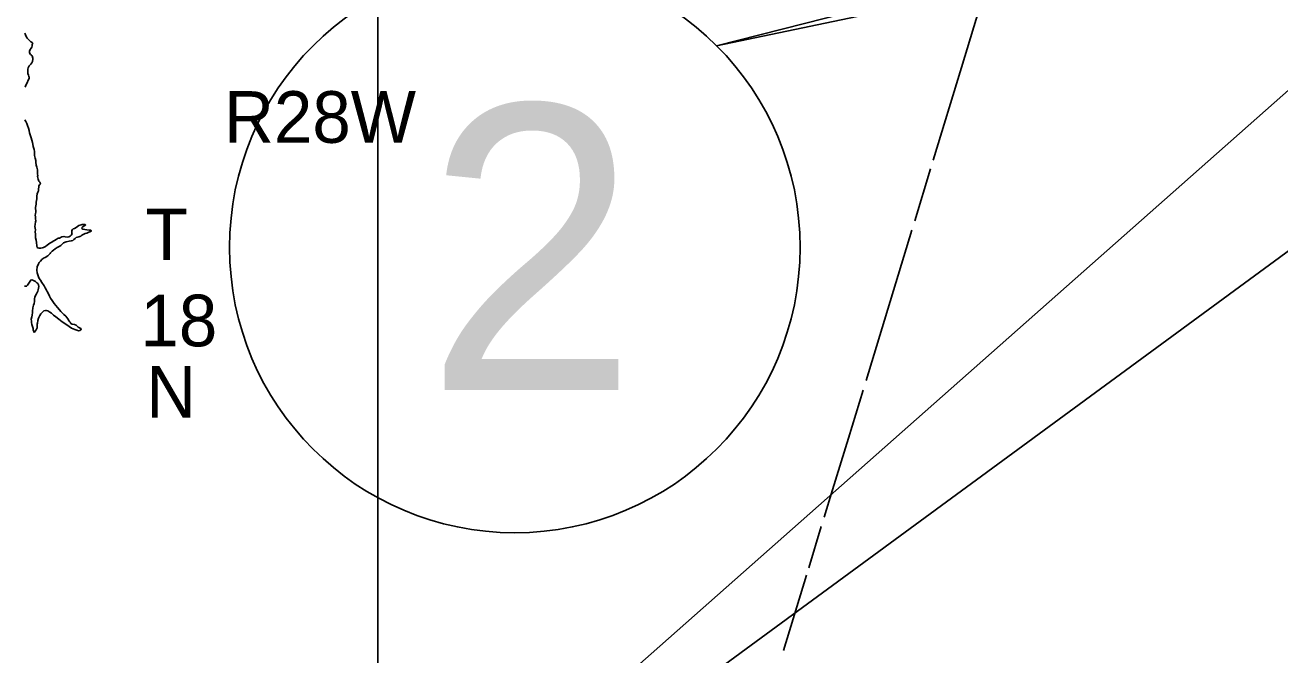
# Model space of a CAD drawing. Extents: x 77230 to 630905, y 790554 to 1662844.
# Drawn here: x 303084 to 333871, y 1521986 to 1537438 of the extents above; entities that cross this region are included whole.
import ezdxf

# ---------------------------------------------------------------- set-up
doc = ezdxf.new("R2010")
doc.units = 0
for name, color, linetype in [('Level 17', 7, 'Continuous'), ('Level 28', 7, 'Continuous'), ('Level 41', 7, 'Continuous'), ('Level 43', 7, 'Continuous')]:
    doc.layers.add(name, color=color, linetype=linetype)

msp = doc.modelspace()

# ---------------------------------------------------------------- linework, layer by layer
at = {"layer": 'Level 17'}
for points in [[(303083, 1535918), (303091, 1535942), (303110, 1535982), (303132, 1536020), (303161, 1536083), (303181, 1536127), (303183, 1536159), (303179, 1536181), (303168, 1536213), (303150, 1536249), (303148, 1536309), (303155, 1536359), (303161, 1536393), (303188, 1536440), (303222, 1536480), (303250, 1536512), (303267, 1536545), (303277, 1536601), (303275, 1536625), (303254, 1536687), (303242, 1536697), (303214, 1536718), (303189, 1536760), (303193, 1536800), (303205, 1536841), (303230, 1536873), (303248, 1536895), (303256, 1536933), (303260, 1536961), (303273, 1536991), (303257, 1537013), (303227, 1537031), (303177, 1537077), (303136, 1537120), (303110, 1537158), (303098, 1537200), (303079, 1537238)], [(303346, 1532855), (303343, 1532962), (303354, 1533044), (303356, 1533094), (303369, 1533176), (303376, 1533244), (303382, 1533302), (303397, 1533341), (303409, 1533373), (303413, 1533415), (303418, 1533467), (303420, 1533491), (303434, 1533515), (303450, 1533536), (303459, 1533552), (303445, 1533586), (303423, 1533613), (303405, 1533657), (303392, 1533723), (303396, 1533751), (303392, 1533783), (303385, 1533827), (303385, 1533889), (303368, 1533951), (303358, 1534003), (303351, 1534073), (303349, 1534120), (303330, 1534171), (303318, 1534237), (303311, 1534289), (303313, 1534336), (303304, 1534388), (303286, 1534457), (303277, 1534517), (303269, 1534559), (303248, 1534619), (303232, 1534671), (303215, 1534723), (303191, 1534793), (303182, 1534853), (303164, 1534907), (303139, 1534971), (303123, 1535023), (303101, 1535071), (303076, 1535114)], [(304310, 1532206), (304340, 1532226), (304400, 1532245), (304448, 1532257), (304480, 1532280), (304555, 1532321), (304597, 1532337), (304633, 1532349), (304690, 1532370), (304712, 1532388), (304696, 1532410), (304656, 1532408), (304602, 1532411), (304546, 1532425), (304502, 1532432), (304480, 1532450), (304488, 1532478), (304523, 1532502), (304551, 1532519), (304567, 1532531), (304555, 1532547), (304517, 1532544), (304485, 1532544), (304457, 1532540), (304399, 1532523), (304366, 1532495), (304334, 1532471), (304300, 1532450), (304264, 1532436), (304245, 1532420), (304231, 1532397), (304231, 1532343), (304235, 1532315), (304218, 1532283), (304190, 1532261), (304156, 1532240), (304114, 1532238), (304070, 1532246), (304036, 1532253), (303988, 1532243), (303931, 1532214), (303899, 1532208), (303847, 1532181), (303807, 1532157), (303770, 1532134), (303742, 1532116), (303688, 1532088), (303658, 1532063), (303629, 1532037), (303583, 1532002), (303535, 1531978), (303505, 1531970), (303471, 1531969), (303428, 1531963), (303398, 1531970), (303383, 1531984), (303371, 1532026), (303362, 1532108), (303352, 1532162), (303343, 1532216), (303343, 1532260), (303343, 1532308), (303334, 1532366), (303336, 1532415), (303325, 1532493), (303333, 1532545), (303338, 1532609), (303344, 1532639), (303339, 1532683), (303339, 1532731), (303335, 1532771), (303340, 1532811), (303346, 1532855)], [(303247, 1530278), (303233, 1530222), (303238, 1530176), (303240, 1530144), (303252, 1530096), (303269, 1530042), (303275, 1530022), (303281, 1529994), (303285, 1529958), (303288, 1529938), (303300, 1529904), (303314, 1529908), (303332, 1529926), (303359, 1529961), (303381, 1530011), (303380, 1530067), (303382, 1530097), (303386, 1530129), (303399, 1530194), (303417, 1530250), (303430, 1530282), (303448, 1530316), (303474, 1530355), (303490, 1530373), (303519, 1530405), (303545, 1530429), (303585, 1530432), (303611, 1530432), (303645, 1530426), (303691, 1530397), (303733, 1530373), (303782, 1530324), (303838, 1530282), (303914, 1530223), (303997, 1530157), (304107, 1530086), (304220, 1530003), (304308, 1529966), (304356, 1529951), (304394, 1529939), (304428, 1529945), (304452, 1529958), (304462, 1529972), (304448, 1529996), (304416, 1530007), (304384, 1530027), (304361, 1530051), (304337, 1530079), (304293, 1530092), (304239, 1530104), (304207, 1530117), (304187, 1530149), (304166, 1530175), (304130, 1530235), (304080, 1530294), (304033, 1530338), (303963, 1530414), (303930, 1530451), (303878, 1530507), (303841, 1530555), (303801, 1530608), (303750, 1530684), (303710, 1530738), (303680, 1530791), (303655, 1530845), (303623, 1530905), (303608, 1530933), (303576, 1530993), (303552, 1531040), (303497, 1531122), (303458, 1531176), (303428, 1531222), (303412, 1531263), (303395, 1531309), (303383, 1531361), (303376, 1531427), (303384, 1531510), (303409, 1531582), (303429, 1531614), (303460, 1531649), (303492, 1531683), (303534, 1531723), (303579, 1531734), (303639, 1531775), (303675, 1531809), (303696, 1531833), (303710, 1531849), (303750, 1531888), (303784, 1531918), (303825, 1531949), (303871, 1531979), (303921, 1532002), (303958, 1532030), (303994, 1532063), (304030, 1532093), (304095, 1532120), (304163, 1532136), (304221, 1532149), (304253, 1532153), (304279, 1532178), (304310, 1532206)], [(303070, 1531032), (303120, 1531030), (303128, 1531040), (303146, 1531060), (303162, 1531083), (303191, 1531129), (303205, 1531157), (303221, 1531179), (303251, 1531188), (303289, 1531174), (303341, 1531145), (303371, 1531115), (303395, 1531095), (303413, 1531065), (303420, 1531025), (303410, 1530985), (303405, 1530941), (303397, 1530907), (303377, 1530876), (303366, 1530842), (303338, 1530802), (303324, 1530760), (303315, 1530720), (303313, 1530676), (303313, 1530653), (303308, 1530609), (303290, 1530563), (303275, 1530503), (303267, 1530423), (303266, 1530383), (303260, 1530320), (303247, 1530278)]]:
    msp.add_lwpolyline(points, dxfattribs=at)
at = {"layer": 'Level 28'}
msp.add_line((311736, 1658884), (311736, 1488604), dxfattribs=at)
at = {"layer": 'Level 41'}
for points in [[(341472, 1542376), (320050, 1536933), (355031, 1544235)], [(341446, 1542356), (307906, 1512690), (336902, 1533972)]]:
    msp.add_lwpolyline(points, dxfattribs=at)
msp.add_circle((315100, 1531983), 7000, dxfattribs=at)
at = {"layer": 'Level 43'}
for p, q in [((322896, 1526039), (322691, 1525367)), ((322620, 1525135), (322313, 1524126)), ((322256, 1523942), (321693, 1522092))]:
    msp.add_line(p, q, dxfattribs=at)
for points in [[(326792, 1538788), (326502, 1537854), (326058, 1536399)], [(326058, 1536399), (325364, 1534121)], [(325300, 1533908), (324912, 1532635)], [(324843, 1532410), (323719, 1528721)], [(323646, 1528481), (323287, 1527303), (322896, 1526039)]]:
    msp.add_lwpolyline(points, dxfattribs=at)

# ---------------------------------------------------------------- texts
at = {"layer": 'Level 28'}
for s, height, p in [('R28W', 1267.2, (307966, 1534550)), ('T', 1267, (306040, 1531671)), ('18', 1267.2, (305914, 1529557)), ('N', 1267, (306056, 1527808))]:
    msp.add_text(s, height=height, dxfattribs=at).set_placement(p)
at = {"layer": 'Level 41'}
msp.add_text('2', height=7000, dxfattribs=at).set_placement((312908, 1528483))

doc.saveas('drawing.dxf')
